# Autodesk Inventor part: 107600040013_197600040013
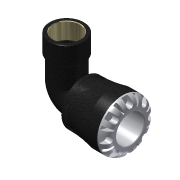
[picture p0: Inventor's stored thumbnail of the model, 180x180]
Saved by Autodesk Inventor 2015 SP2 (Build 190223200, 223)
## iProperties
Created: 2016-12
Part Number: 107600040013_197600040013
Material: PVC-Piping
Description: PLASSON 90° ELBOW WITH FEMALE INTEGRAL BRASS 40X1.1/4" SERIES 1
Document SubType Name: Modeling
Designer: KIM
Mass: 664.223 g
Surface Area: 733.008 cm^2
Volume: 474.445 cm^3
Density: 1.4 g/cm^3
Appearance: Black Cast
Author: KIM
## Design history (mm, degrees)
derived "1076.ipt"
feature "Solid1::1076.ipt"
tag "TaggingFeature1"
body "Solid1"
other parameters: "d1" = 30.24, "d8" = 61.6, "d13" = 8, "d14" = 8, "d15" = 0, "d17" = 360 deg, "d19" = 8 deg, "d20" = 0.8, "d21" = 0.8, "d22" = 8 deg, "d24" = 0, "d26" = 360 deg, "d33" = 7, "d51" = 0.7, "d54" = 14, "d55" = 8.8, "d57" = 15.68, "d58" = 0, "d74" = 0, "d78" = 72, "d82" = 0.8, "d115" = 360 deg, "d207" = 90 deg, "d228" = 11.9, "d248" = 4.32, "d270" = 107, "d279" = 67, "d281" = 5.8428, "d294" = 38.952, "d295" = 21, "d296" = 23.1, "d297" = 35.0568, "d299" = 45.57384, "d300" = 35.0568, "d301" = 0, "d302" = 0, "d306" = 2.53188, "d309" = 72.72, "d310" = 8.01308, "d312" = 15 deg, "d313" = 0.56, "d314" = 8.208, "d315" = 0.35, "l_" = 72, "A_" = 107, "A_1" = 67, "l_2" = 21, "Rp_" = 38.952, "d9" = 10, "d298" = 50.6376
